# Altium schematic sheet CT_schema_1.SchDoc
size 699 x 429 mm
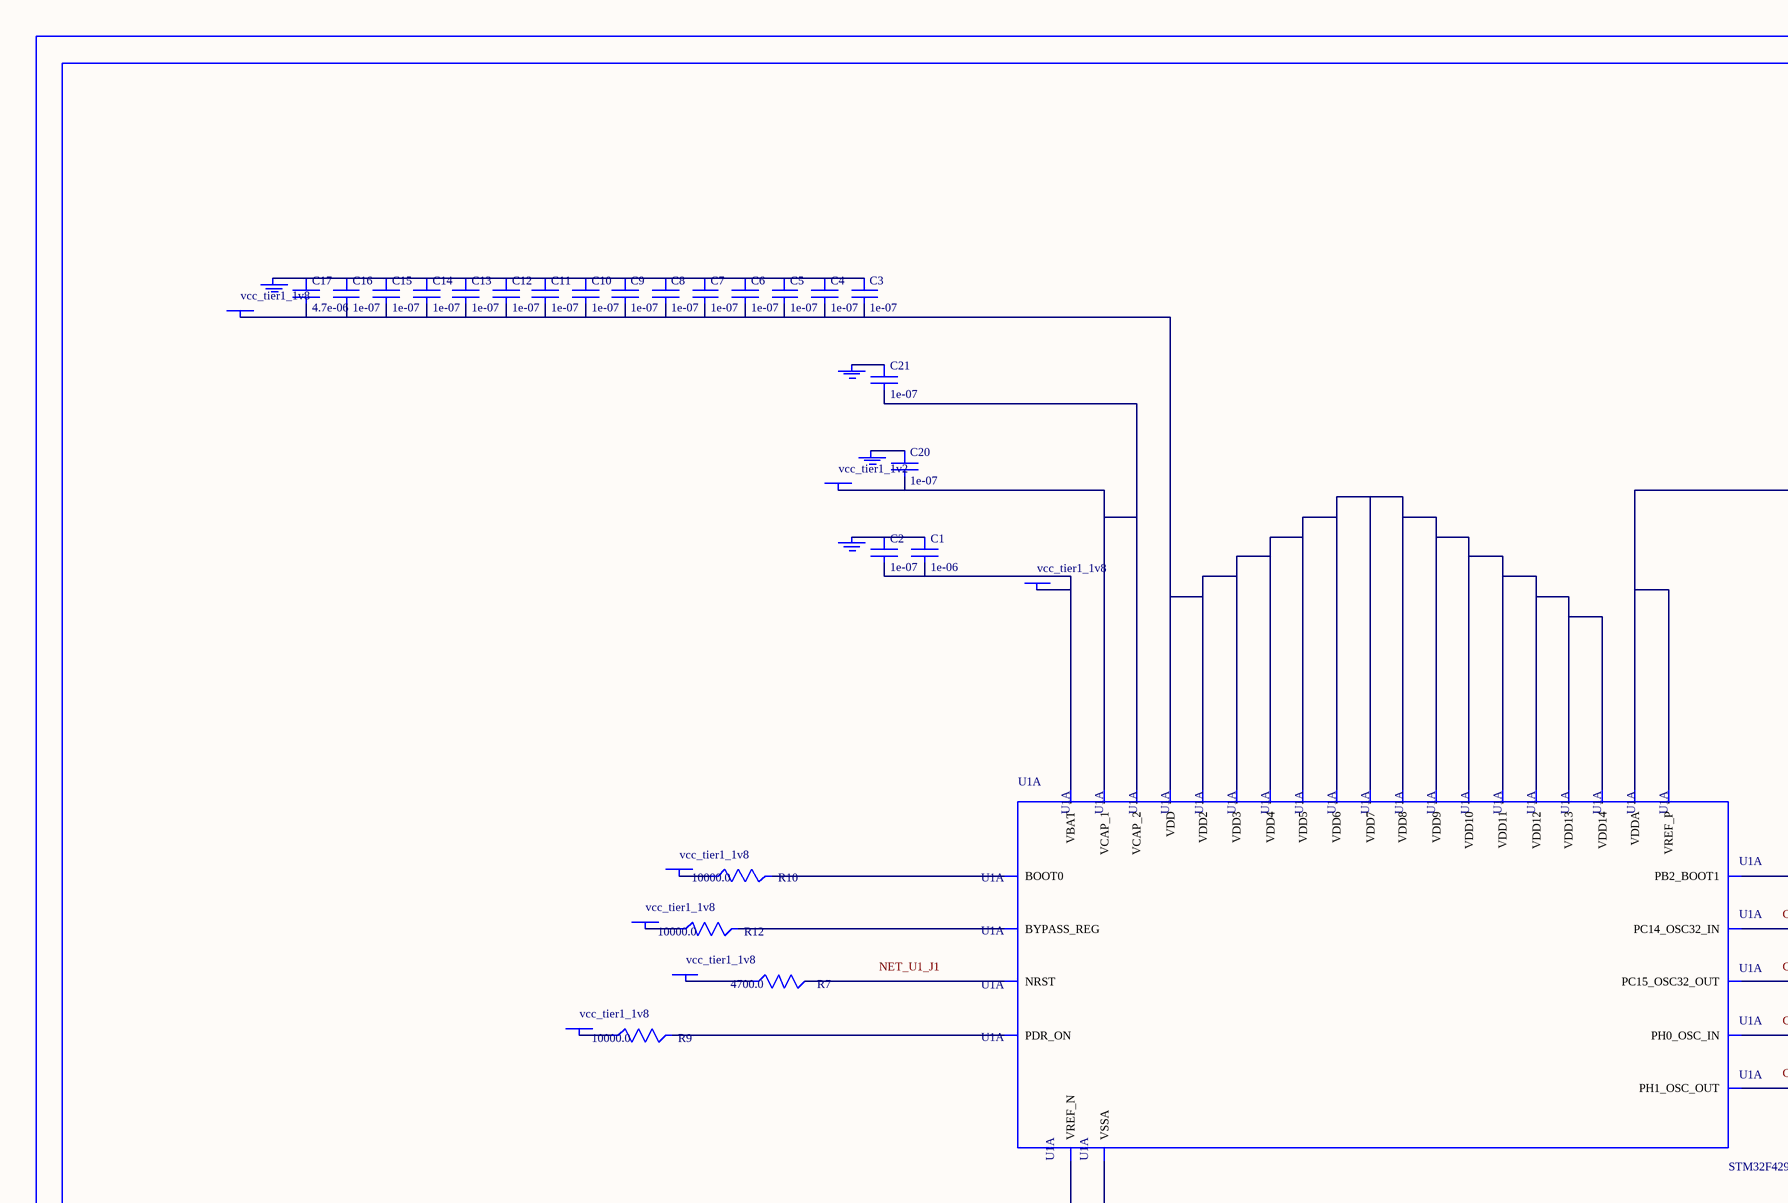
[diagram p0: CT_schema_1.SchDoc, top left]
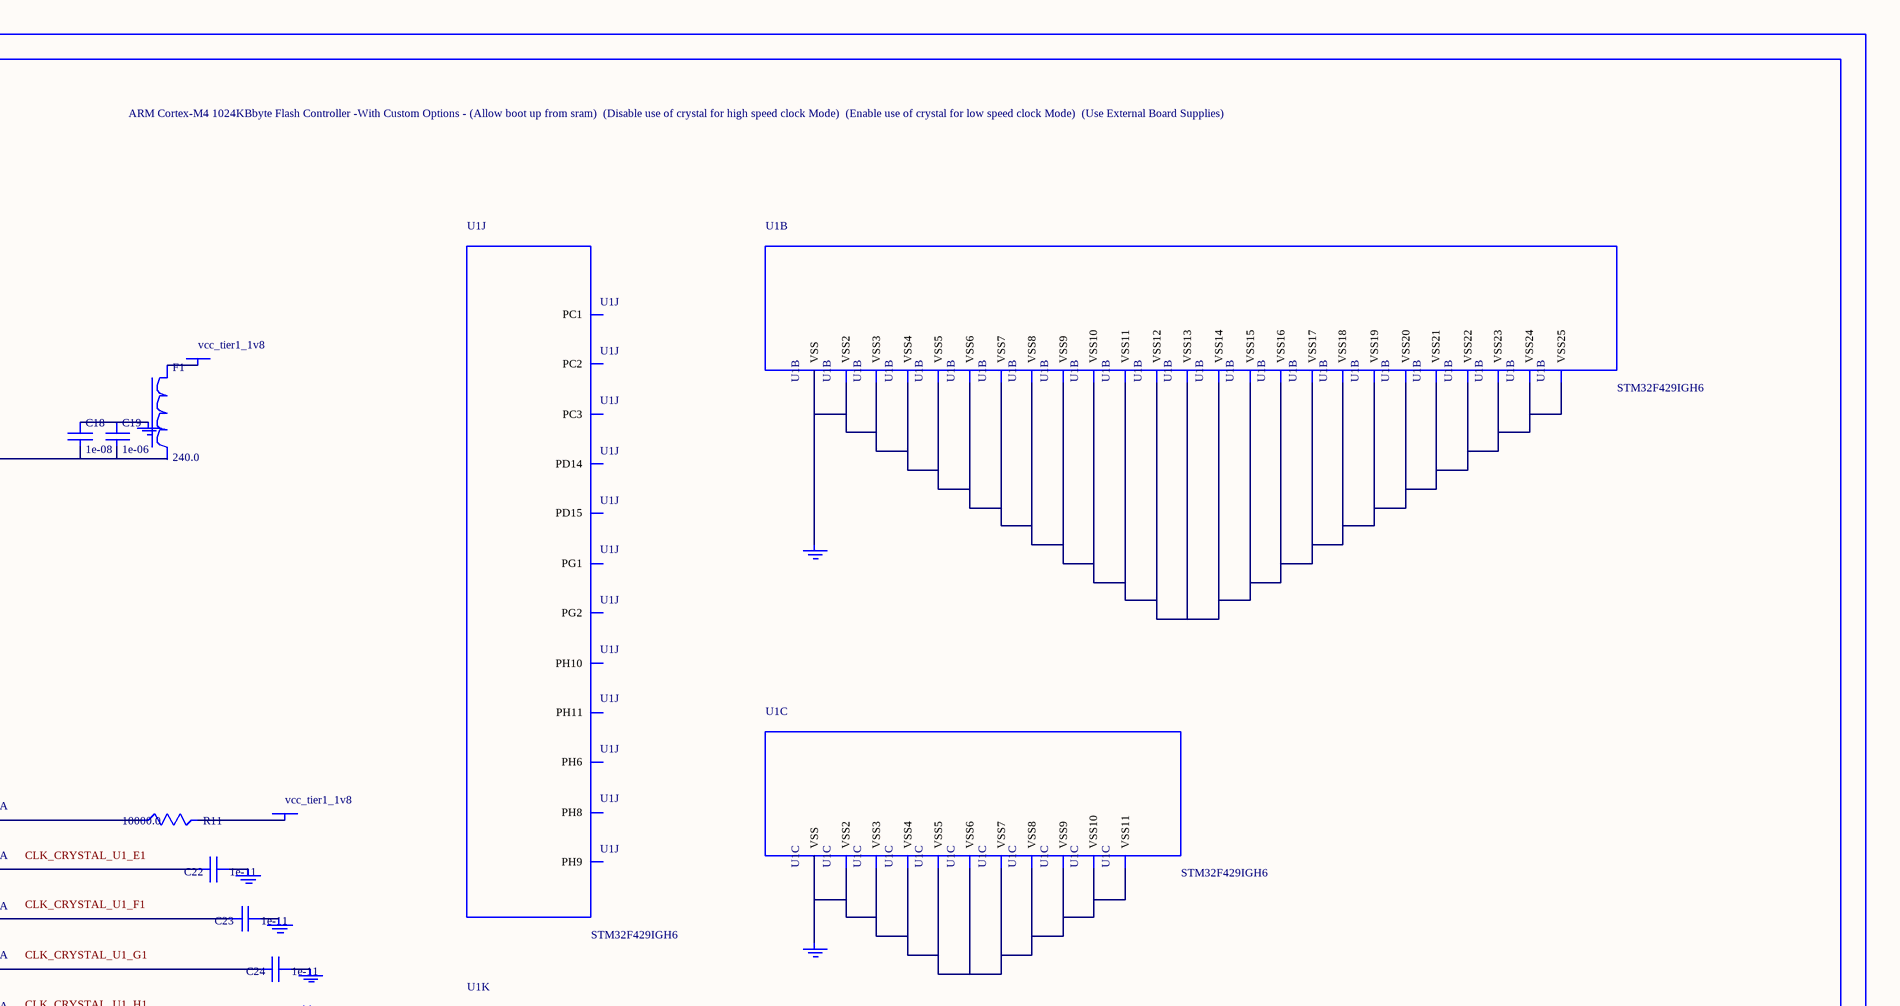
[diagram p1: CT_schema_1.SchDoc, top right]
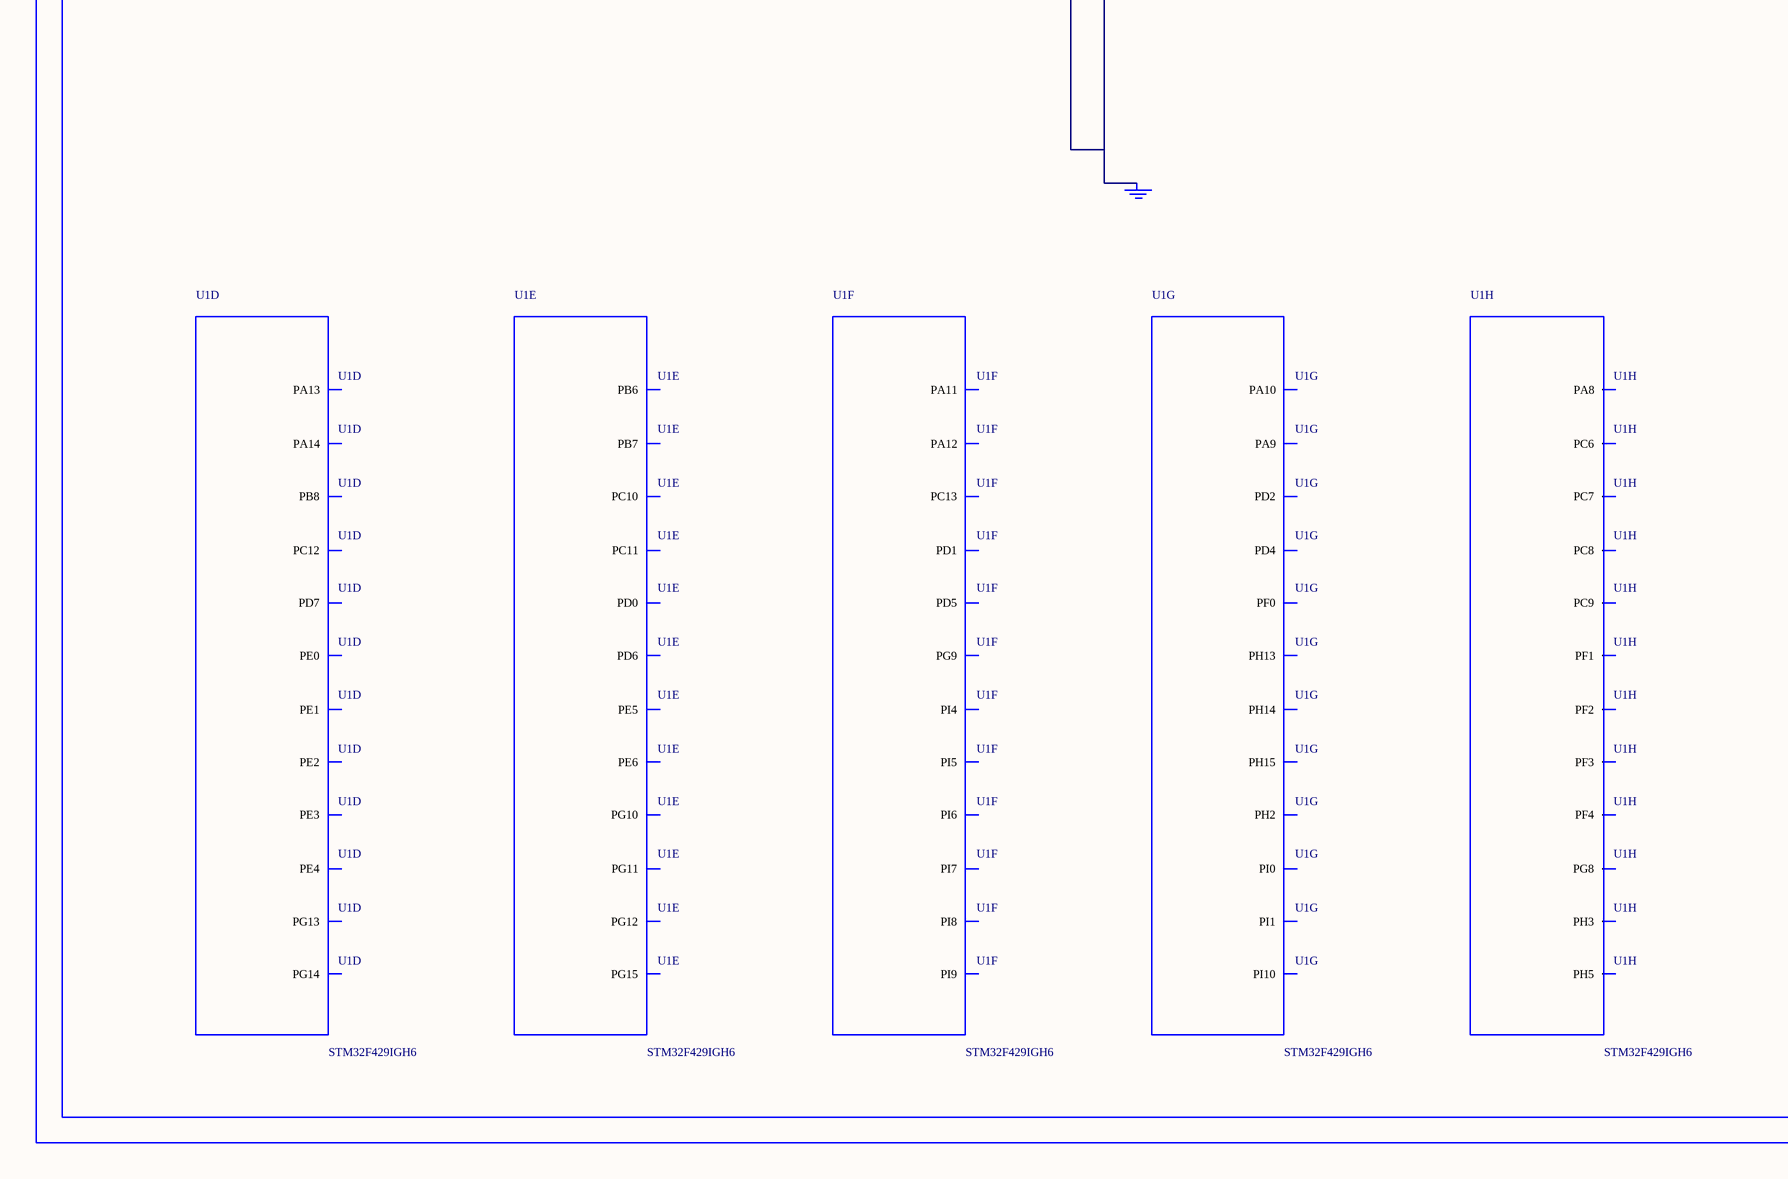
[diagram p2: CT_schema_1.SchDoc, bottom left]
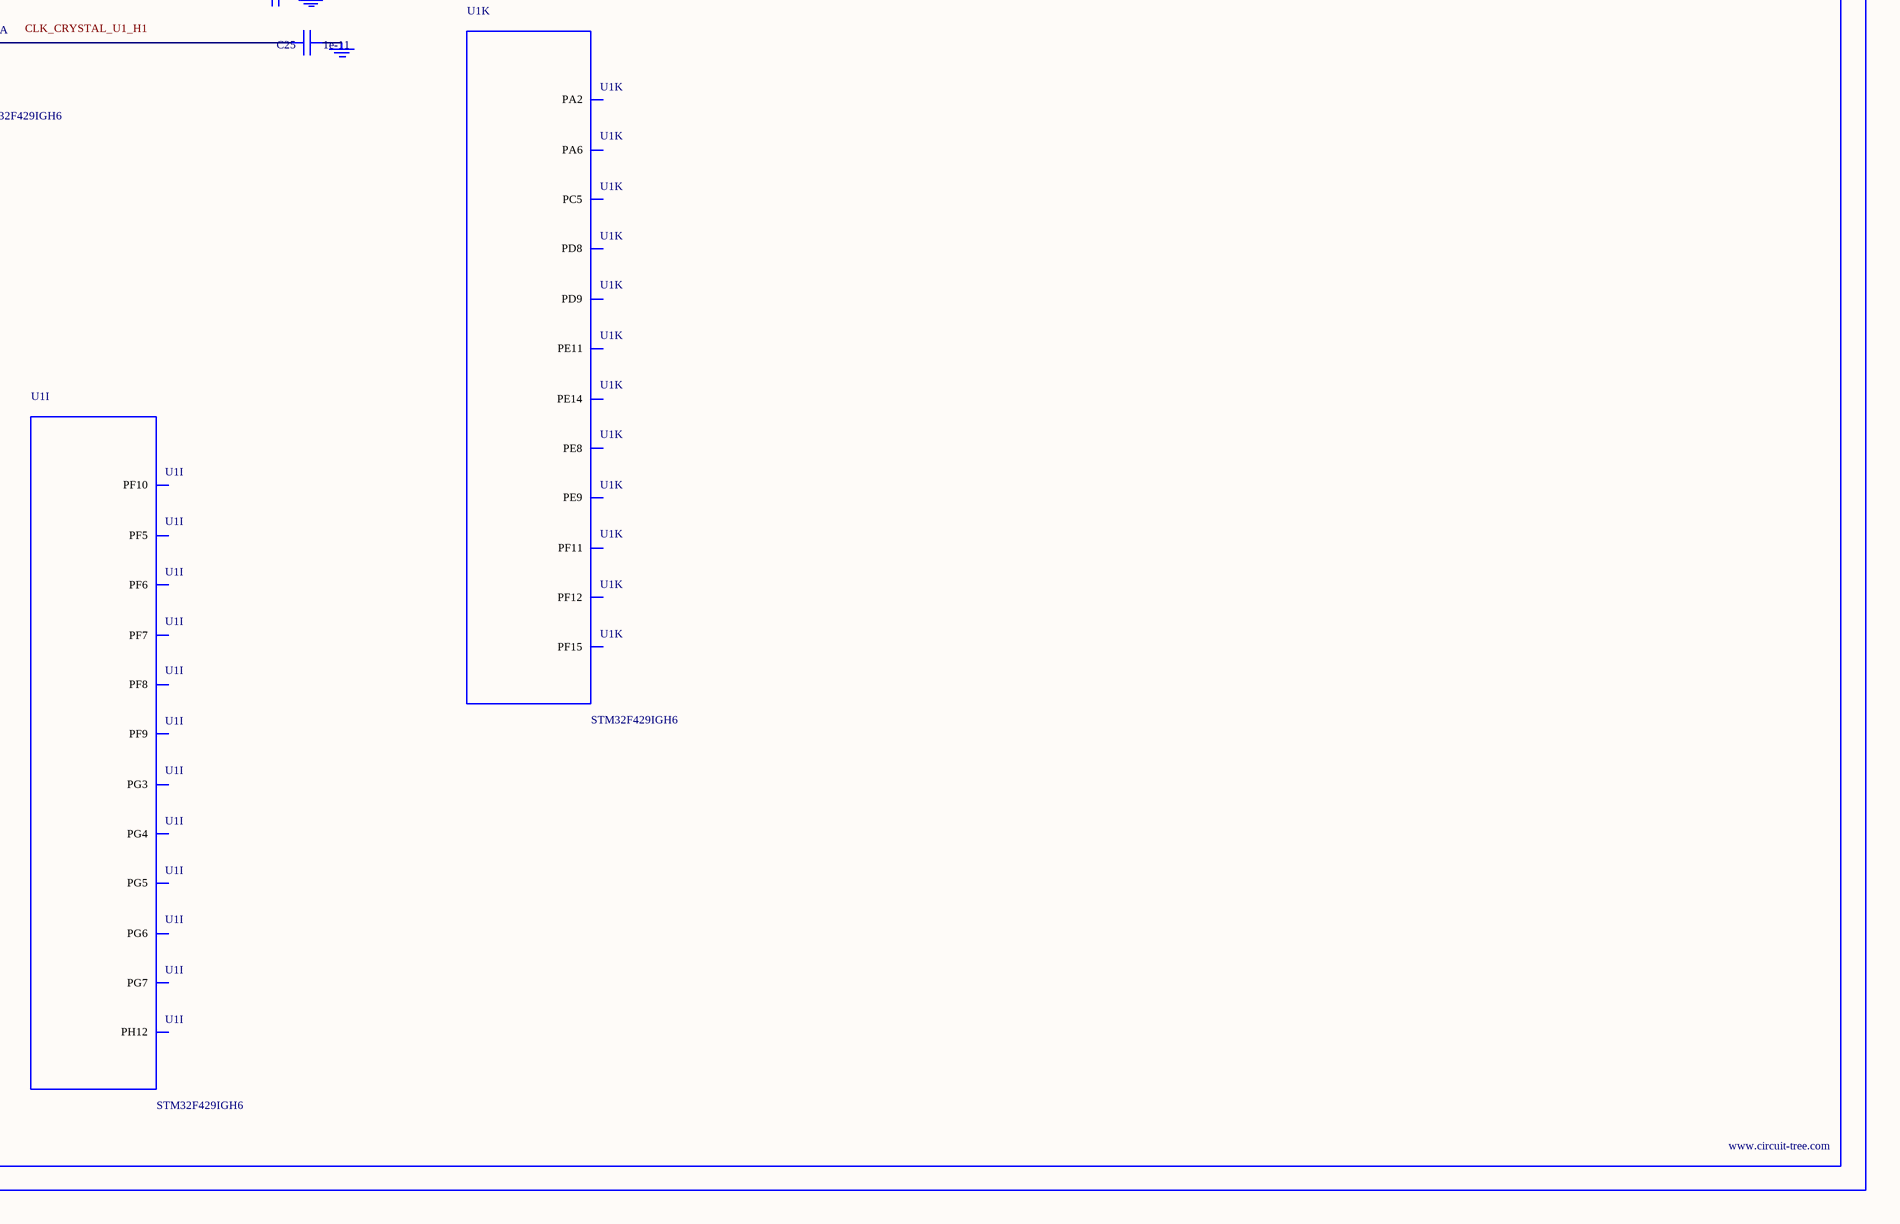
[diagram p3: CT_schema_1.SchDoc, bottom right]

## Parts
BORDER0  (no value)
C1  1e-06  [C0603]
C2  1e-07  [C0603]
C3  1e-07  [C0603]
C4  1e-07  [C0603]
C5  1e-07  [C0603]
C6  1e-07  [C0603]
C7  1e-07  [C0603]
C8  1e-07  [C0603]
C9  1e-07  [C0603]
C10  1e-07  [C0603]
C11  1e-07  [C0603]
C12  1e-07  [C0603]
C13  1e-07  [C0603]
C14  1e-07  [C0603]
C15  1e-07  [C0603]
C16  1e-07  [C0603]
C17  4.7e-06  [C0603]
C18  1e-08  [C0603]
C19  1e-06  [C0603]
C20  1e-07  [C0402]
C21  1e-07  [C0402]
C22  1e-11  [C0402]
C23  1e-11  [C0402]
C24  1e-11  [C0402]
C25  1e-11  [C0402]
F1  240.0  [L0603]
GND_INSTANCE_0_0  (no value)
GND_INSTANCE_0_1  (no value)
GND_INSTANCE_0_2  (no value)
GND_INSTANCE_0_3  (no value)
GND_INSTANCE_0_4  (no value)
GND_INSTANCE_0_5  (no value)
GND_INSTANCE_0_6  (no value)
GND_INSTANCE_0_7  (no value)
GND_INSTANCE_0_8  (no value)
GND_INSTANCE_0_9  (no value)
GND_INSTANCE_0_10  (no value)
GND_INSTANCE_0_11  (no value)
POWER_INSTANCE_0_0  vcc_tier1_1v8
POWER_INSTANCE_0_1  vcc_tier1_1v8
POWER_INSTANCE_0_2  vcc_tier1_1v8
POWER_INSTANCE_0_3  vcc_tier1_1v8
POWER_INSTANCE_0_4  vcc_tier1_1v8
POWER_INSTANCE_0_5  vcc_tier1_1v8
POWER_INSTANCE_0_6  vcc_tier1_1v8
POWER_INSTANCE_0_7  vcc_tier1_1v2
POWER_INSTANCE_0_8  vcc_tier1_1v8
R7  4700.0  [R0603]
R9  10000.0  [R0603]
R10  10000.0  [R0603]
R11  10000.0  [R0603]
R12  10000.0  [R0603]
U1  STM32F429IGH6  [UFBGA176_25]  (parts A,B,C,D,E,F,G,H,I,J,K of 15)

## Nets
NetC1_1: C1.1 C2.1 GND_INSTANCE_0_0.0(GND)
NetC1_2: C1.2 C2.2 POWER_INSTANCE_0_0.0(PWR) U1.C1(VBAT)
NetC3_1: C3.1 C4.1 C5.1 C6.1 C7.1 C8.1 C9.1 C10.1 C11.1 C12.1 C13.1 C14.1 C15.1 C16.1 C17.1 GND_INSTANCE_0_2.0(GND)
NetC3_2: C3.2 C4.2 C5.2 C6.2 C7.2 C8.2 C9.2 C10.2 C11.2 C12.2 C13.2 C14.2 C15.2 C16.2 C17.2 POWER_INSTANCE_0_2.0(PWR) U1.C5(VDD) U1.C7(VDD2) U1.C8(VDD3) U1.C9(VDD4) U1.F3(VDD5) U1.G3(VDD7) U1.G13(VDD6) U1.H13(VDD8) U1.J12(VDD9) U1.J13(VDD10) U1.K4(VDD11) U1.N8(VDD13) U1.N9(VDD14) U1.N10(VDD12)
NetC18_1: C18.1 C19.1 GND_INSTANCE_0_1.0(GND)
NetC18_2: C18.2 C19.2 U1.P1(VREF_P) U1.R1(VDDA)
NetC20_1: C20.1 GND_INSTANCE_0_3.0(GND)
NetC20_2: C20.2 C21.2 POWER_INSTANCE_0_7.0(PWR) U1.F13(VCAP_2) U1.M10(VCAP_1)
NetC21_1: C21.1 GND_INSTANCE_0_4.0(GND)
NetC22_1: C22.1 GND_INSTANCE_0_5.0(GND)
NetC22_2: C22.2 U1.E1(PC14_OSC32_IN)
NetC23_1: C23.1 GND_INSTANCE_0_6.0(GND)
NetC23_2: C23.2 U1.F1(PC15_OSC32_OUT)
NetC24_1: C24.1 GND_INSTANCE_0_7.0(GND)
NetC24_2: C24.2 U1.G1(PH0_OSC_IN)
NetC25_1: C25.1 GND_INSTANCE_0_8.0(GND)
NetC25_2: C25.2 U1.H1(PH1_OSC_OUT)
NetF1_1: F1.1 POWER_INSTANCE_0_1.0(PWR)
NetGND_INSTANCE_0_9_0: GND_INSTANCE_0_9.0(GND) U1.M1(VSSA) U1.N1(VREF_N)
NetGND_INSTANCE_0_10_0: GND_INSTANCE_0_10.0(GND) U1.D5(VSS) U1.D7(VSS2) U1.D8(VSS3) U1.D9(VSS4) U1.F2(VSS7) U1.F6(VSS8) U1.F7(VSS9) U1.F8(VSS10) U1.F9(VSS11) U1.F10(VSS5) U1.F12(VSS6) U1.G2(VSS14) U1.G6(VSS15) U1.G7(VSS16) U1.G8(VSS17) U1.G9(VSS18) U1.G10(VSS12) U1.G12(VSS13) U1.H6(VSS21) U1.H7(VSS22) U1.H8(VSS23) U1.H9(VSS24) U1.H10(VSS19) U1.H12(VSS20) U1.J10(VSS25)
NetGND_INSTANCE_0_11_0: GND_INSTANCE_0_11.0(GND) U1.J6(VSS) U1.J7(VSS2) U1.J8(VSS3) U1.J9(VSS4) U1.K6(VSS6) U1.K7(VSS7) U1.K8(VSS8) U1.K9(VSS9) U1.K10(VSS5) U1.M8(VSS10) U1.M9(VSS11)
NetPOWER_INSTANCE_0_3_0: POWER_INSTANCE_0_3.0(PWR) R9.1
NetPOWER_INSTANCE_0_4_0: POWER_INSTANCE_0_4.0(PWR) R10.1
NetPOWER_INSTANCE_0_5_0: POWER_INSTANCE_0_5.0(PWR) R11.2
NetPOWER_INSTANCE_0_6_0: POWER_INSTANCE_0_6.0(PWR) R12.1
NetPOWER_INSTANCE_0_8_0: POWER_INSTANCE_0_8.0(PWR) R7.1
NetR7_2: R7.2 U1.J1(NRST)
NetR9_2: R9.2 U1.C6(PDR_ON)
NetR10_2: R10.2 U1.D6(BOOT0)
NetR11_1: R11.1 U1.M6(PB2_BOOT1)
NetR12_2: R12.2 U1.L4(BYPASS_REG)

Not connected (* = marked no-connect by the designer): F1 2; U1 A1(PE3) A2(PE2) A3(PE1) A4(PE0) A5(PB8) A7(PG14) A8(PG13) A11(PD7) A12(PC12) A14(PA14) A15(PA13) B1(PE4) B2(PE5) B3(PE6) B5(PB7) B6(PB6) B7(PG15) B8(PG12) B9(PG11) B10(PG10) B11(PD6) B12(PD0) B13(PC11) B14(PC10) B15(PA12) C2(PI7) C3(PI6) C4(PI5) C10(PG9) C11(PD5) C12(PD1) C15(PA11) D1(PC13) D2(PI8) D3(PI9) D4(PI4) D10(PD4) D12(PD2) D13(PH15) D14(PI1) D15(PA10) E2(PF0) E3(PI10) E12(PH13) E13(PH14) E14(PI0) E15(PA9) F4(PH2) F14(PC9) F15(PA8) G4(PH3) G14(PC8) G15(PC7) H2(PF2) H3(PF1) H14(PG8) H15(PC6) J2(PF3) J3(PF4) J4(PH5) J14(PG7) J15(PG6) K1(PF7) K2(PF6) K3(PF5) K12(PH12) K13(PG5) K14(PG4) K15(PG3) L1(PF10) L2(PF9) L3(PF8) L12(PH11) L13(PH10) L14(PD15) L15(PG2) M3(PC1) M4(PC2) M5(PC3) M7(PG1) M11(PH6) M12(PH8) M13(PH9) M14(PD14) P2(PA2) P3(PA6) P5(PC5) P6(PF12) P7(PF15) P8(PE8) P9(PE9) P10(PE11) P11(PE14) P14(PD9) P15(PD8) R6(PF11)

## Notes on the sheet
- Labels drawn without touching a wire or pin: CLK_CRYSTAL_U1_E1, CLK_CRYSTAL_U1_F1, CLK_CRYSTAL_U1_G1, CLK_CRYSTAL_U1_H1, NET_U1_J1

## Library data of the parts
BORDER0 = BORDER_PAGE0
C1 C19 = C0603C105K3RACTU
C2-C16 = 06035C104K4Z2A
C17 = GRM188R6YA475KE15D
C18 = 06035C103K4Z2A
C20 C21 = C0402C104K3RACTU
C22-C25 = C0402C100K3GACTU
F1 = Z0603C241ASMST
GND_INSTANCE_0_0-GND_INSTANCE_0_11 = GND
POWER_INSTANCE_0_0-POWER_INSTANCE_0_8 = PWR
R7 = RC0603JR-074K7L
R9-R12 = RC0603JR-0710KL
